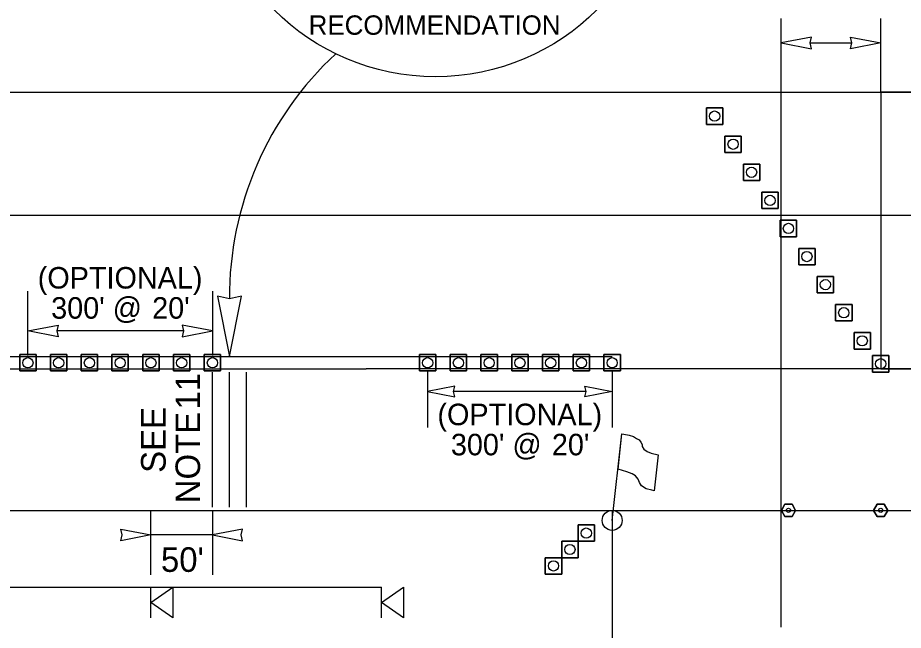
# Model space of a CAD drawing. Extents: x 99998.9 to 100095.7, y 99995 to 100010.7.
# Drawn here: x 100042.344 to 100045.223, y 100005.742 to 100007.734 of the extents above; entities that cross this region are included whole.
import ezdxf

# ---------------------------------------------------------------- set-up
doc = ezdxf.new("R2010")
doc.units = 0
for name, color, linetype in [('RD_ED_ShoulderPavedEdge', 7, 'Continuous'), ('RD_MK_LineDblYellowCenter', 7, 'Continuous'), ('RD_MK_LineEdgeWhite', 7, 'Continuous'), ('RD_MK_LineNoPass', 7, 'Continuous'), ('RD_MK_LineSkipCenter', 7, 'Continuous'), ('TR_WZ_FlaggingStation', 7, 'Continuous'), ('TR_WZ_PortableSignMountBlk-Org', 7, 'Continuous'), ('TR_WZ_TrafficCone', 7, 'Continuous'), ('TR_WZ_TubularMarker', 7, 'Continuous'), ('TR_WZ_WorkZoneDetails', 7, 'Continuous'), ('TR_WZ_WorkZoneTextCurrent', 7, 'Continuous')]:
    doc.layers.add(name, color=color, linetype=linetype)

msp = doc.modelspace()

# ---------------------------------------------------------------- linework, layer by layer
at = {"layer": 'RD_ED_ShoulderPavedEdge'}
msp.add_line((100040.1076, 100007.4923), (100055.6424, 100007.4923), dxfattribs=at)
at = {"layer": 'RD_MK_LineDblYellowCenter'}
for p, q in [((100040.1282, 100006.6323), (100043.4767, 100006.6323)), ((100040.0869, 100006.5923), (100043.4767, 100006.5923))]:
    msp.add_line(p, q, dxfattribs=at)
at = {"layer": 'RD_MK_LineEdgeWhite'}
for p, q in [((100040.1076, 100007.0923), (100055.6424, 100007.0923)), ((100040.1076, 100006.1323), (100055.6424, 100006.1323))]:
    msp.add_line(p, q, dxfattribs=at)
at = {"layer": 'RD_MK_LineNoPass'}
msp.add_line((100043.4767, 100006.6323), (100044.2767, 100006.6323), dxfattribs=at)
at = {"layer": 'RD_MK_LineSkipCenter'}
msp.add_lwpolyline([(100051.15, 100006.5923), (100043.4767, 100006.5923)], dxfattribs=at)
at = {"layer": 'TR_WZ_FlaggingStation'}
for p, q in [((100044.2767, 100006.0998), (100044.3087, 100006.3808)), ((100044.2957, 100006.2667), (100044.3087, 100006.3811)), ((100044.4267, 100006.3133), (100044.4134, 100006.1961)), ((100044.2957, 100006.2667), (100044.2957, 100006.2667))]:
    msp.add_line(p, q, dxfattribs=at)
for points in [[(100044.3087, 100006.3811), (100044.3145, 100006.3798), (100044.3323, 100006.3764), (100044.3461, 100006.3722), (100044.3558, 100006.3661), (100044.3643, 100006.3614), (100044.37, 100006.3546), (100044.3743, 100006.3467), (100044.3748, 100006.3405), (100044.3802, 100006.3313), (100044.391, 100006.3239), (100044.4034, 100006.3187), (100044.4267, 100006.3133)], [(100044.4134, 100006.1961), (100044.4052, 100006.1975), (100044.3876, 100006.2021), (100044.3719, 100006.2126), (100044.3654, 100006.2232), (100044.3615, 100006.2335), (100044.3524, 100006.2444), (100044.3414, 100006.2506), (100044.3241, 100006.2577), (100044.2957, 100006.2667)]]:
    msp.add_lwpolyline(points, dxfattribs=at)
msp.add_circle((100044.2767, 100006.0998), 0.0325, dxfattribs=at)
at = {"layer": 'TR_WZ_PortableSignMountBlk-Org'}
for p, q in [((100042.7767, 100005.7824), (100042.7767, 100005.8824)), ((100043.5267, 100005.7824), (100043.5267, 100005.8824))]:
    msp.add_line(p, q, dxfattribs=at)
for points in [[(100042.7767, 100005.8323), (100042.8485, 100005.8824), (100042.8485, 100005.7824)], [(100043.5267, 100005.8323), (100043.5985, 100005.8824), (100043.5985, 100005.7824)]]:
    msp.add_lwpolyline(points, close=True, dxfattribs=at)
at = {"layer": 'TR_WZ_TrafficCone'}
for points in [[(100044.6367, 100007.4411), (100044.5834, 100007.4411), (100044.5834, 100007.3877), (100044.6367, 100007.3877), (100044.6367, 100007.4411)], [(100044.6367, 100007.3877), (100044.5834, 100007.3877), (100044.5834, 100007.4411), (100044.6367, 100007.4411), (100044.6367, 100007.3877)], [(100044.6967, 100007.3497), (100044.6434, 100007.3497), (100044.6434, 100007.2964), (100044.6967, 100007.2964), (100044.6967, 100007.3497)], [(100044.6967, 100007.2964), (100044.6434, 100007.2964), (100044.6434, 100007.3497), (100044.6967, 100007.3497), (100044.6967, 100007.2964)], [(100044.7567, 100007.2584), (100044.7034, 100007.2584), (100044.7034, 100007.2051), (100044.7567, 100007.2051), (100044.7567, 100007.2584)], [(100044.7567, 100007.2051), (100044.7034, 100007.2051), (100044.7034, 100007.2584), (100044.7567, 100007.2584), (100044.7567, 100007.2051)], [(100044.8167, 100007.1671), (100044.7634, 100007.1671), (100044.7634, 100007.1137), (100044.8167, 100007.1137), (100044.8167, 100007.1671)], [(100044.8167, 100007.1137), (100044.7634, 100007.1137), (100044.7634, 100007.1671), (100044.8167, 100007.1671), (100044.8167, 100007.1137)], [(100044.8234, 100007.0757), (100044.8767, 100007.0757), (100044.8767, 100007.0224), (100044.8234, 100007.0224), (100044.8234, 100007.0757)], [(100044.8234, 100007.0224), (100044.8767, 100007.0224), (100044.8767, 100007.0757), (100044.8234, 100007.0757), (100044.8234, 100007.0224)], [(100044.8834, 100006.9844), (100044.9367, 100006.9844), (100044.9367, 100006.9311), (100044.8834, 100006.9311), (100044.8834, 100006.9844)], [(100044.8834, 100006.9311), (100044.9367, 100006.9311), (100044.9367, 100006.9844), (100044.8834, 100006.9844), (100044.8834, 100006.9311)], [(100044.9434, 100006.8931), (100044.9967, 100006.8931), (100044.9967, 100006.8397), (100044.9434, 100006.8397), (100044.9434, 100006.8931)], [(100044.9434, 100006.8397), (100044.9967, 100006.8397), (100044.9967, 100006.8931), (100044.9434, 100006.8931), (100044.9434, 100006.8397)], [(100045.0034, 100006.8017), (100045.0567, 100006.8017), (100045.0567, 100006.7484), (100045.0034, 100006.7484), (100045.0034, 100006.8017)], [(100045.0034, 100006.7484), (100045.0567, 100006.7484), (100045.0567, 100006.8017), (100045.0034, 100006.8017), (100045.0034, 100006.7484)], [(100045.0634, 100006.7104), (100045.1167, 100006.7104), (100045.1167, 100006.6571), (100045.0634, 100006.6571), (100045.0634, 100006.7104)], [(100045.0634, 100006.6571), (100045.1167, 100006.6571), (100045.1167, 100006.7104), (100045.0634, 100006.7104), (100045.0634, 100006.6571)], [(100042.4033, 100006.639), (100042.35, 100006.639), (100042.35, 100006.5857), (100042.4033, 100006.5857), (100042.4033, 100006.639)], [(100042.4033, 100006.5857), (100042.35, 100006.5857), (100042.35, 100006.639), (100042.4033, 100006.639), (100042.4033, 100006.5857)], [(100042.5033, 100006.639), (100042.45, 100006.639), (100042.45, 100006.5857), (100042.5033, 100006.5857), (100042.5033, 100006.639)], [(100042.5033, 100006.5857), (100042.45, 100006.5857), (100042.45, 100006.639), (100042.5033, 100006.639), (100042.5033, 100006.5857)], [(100042.6033, 100006.639), (100042.55, 100006.639), (100042.55, 100006.5857), (100042.6033, 100006.5857), (100042.6033, 100006.639)], [(100042.6033, 100006.5857), (100042.55, 100006.5857), (100042.55, 100006.639), (100042.6033, 100006.639), (100042.6033, 100006.5857)], [(100042.7033, 100006.639), (100042.65, 100006.639), (100042.65, 100006.5857), (100042.7033, 100006.5857), (100042.7033, 100006.639)], [(100042.7033, 100006.5857), (100042.65, 100006.5857), (100042.65, 100006.639), (100042.7033, 100006.639), (100042.7033, 100006.5857)], [(100042.8033, 100006.639), (100042.75, 100006.639), (100042.75, 100006.5857), (100042.8033, 100006.5857), (100042.8033, 100006.639)], [(100042.8033, 100006.5857), (100042.75, 100006.5857), (100042.75, 100006.639), (100042.8033, 100006.639), (100042.8033, 100006.5857)], [(100042.9033, 100006.639), (100042.85, 100006.639), (100042.85, 100006.5857), (100042.9033, 100006.5857), (100042.9033, 100006.639)], [(100042.9033, 100006.5857), (100042.85, 100006.5857), (100042.85, 100006.639), (100042.9033, 100006.639), (100042.9033, 100006.5857)], [(100043.0033, 100006.639), (100042.95, 100006.639), (100042.95, 100006.5857), (100043.0033, 100006.5857), (100043.0033, 100006.639)], [(100043.0033, 100006.5857), (100042.95, 100006.5857), (100042.95, 100006.639), (100043.0033, 100006.639), (100043.0033, 100006.5857)], [(100043.7033, 100006.639), (100043.65, 100006.639), (100043.65, 100006.5857), (100043.7033, 100006.5857), (100043.7033, 100006.639)], [(100043.7033, 100006.5857), (100043.65, 100006.5857), (100043.65, 100006.639), (100043.7033, 100006.639), (100043.7033, 100006.5857)], [(100043.8033, 100006.639), (100043.75, 100006.639), (100043.75, 100006.5857), (100043.8033, 100006.5857), (100043.8033, 100006.639)], [(100043.8033, 100006.5857), (100043.75, 100006.5857), (100043.75, 100006.639), (100043.8033, 100006.639), (100043.8033, 100006.5857)], [(100043.9033, 100006.639), (100043.85, 100006.639), (100043.85, 100006.5857), (100043.9033, 100006.5857), (100043.9033, 100006.639)], [(100043.9033, 100006.5857), (100043.85, 100006.5857), (100043.85, 100006.639), (100043.9033, 100006.639), (100043.9033, 100006.5857)], [(100044.0033, 100006.639), (100043.95, 100006.639), (100043.95, 100006.5857), (100044.0033, 100006.5857), (100044.0033, 100006.639)], [(100044.0033, 100006.5857), (100043.95, 100006.5857), (100043.95, 100006.639), (100044.0033, 100006.639), (100044.0033, 100006.5857)], [(100044.1033, 100006.639), (100044.05, 100006.639), (100044.05, 100006.5857), (100044.1033, 100006.5857), (100044.1033, 100006.639)], [(100044.1033, 100006.5857), (100044.05, 100006.5857), (100044.05, 100006.639), (100044.1033, 100006.639), (100044.1033, 100006.5857)], [(100044.2033, 100006.639), (100044.15, 100006.639), (100044.15, 100006.5857), (100044.2033, 100006.5857), (100044.2033, 100006.639)], [(100044.2033, 100006.5857), (100044.15, 100006.5857), (100044.15, 100006.639), (100044.2033, 100006.639), (100044.2033, 100006.5857)], [(100044.3033, 100006.639), (100044.25, 100006.639), (100044.25, 100006.5857), (100044.3033, 100006.5857), (100044.3033, 100006.639)], [(100044.3033, 100006.5857), (100044.25, 100006.5857), (100044.25, 100006.639), (100044.3033, 100006.639), (100044.3033, 100006.5857)], [(100045.1234, 100006.6357), (100045.1767, 100006.6357), (100045.1767, 100006.5823), (100045.1234, 100006.5823), (100045.1234, 100006.6357)], [(100045.1234, 100006.5823), (100045.1767, 100006.5823), (100045.1767, 100006.6357), (100045.1234, 100006.6357), (100045.1234, 100006.5823)], [(100044.166, 100006.085), (100044.2193, 100006.085), (100044.2193, 100006.0317), (100044.166, 100006.0317), (100044.166, 100006.085)], [(100044.166, 100006.0317), (100044.2193, 100006.0317), (100044.2193, 100006.085), (100044.166, 100006.085), (100044.166, 100006.0317)], [(100044.1127, 100006.0317), (100044.166, 100006.0317), (100044.166, 100005.9783), (100044.1127, 100005.9783), (100044.1127, 100006.0317)], [(100044.1127, 100005.9783), (100044.166, 100005.9783), (100044.166, 100006.0317), (100044.1127, 100006.0317), (100044.1127, 100005.9783)], [(100044.0593, 100005.9783), (100044.1127, 100005.9783), (100044.1127, 100005.925), (100044.0593, 100005.925), (100044.0593, 100005.9783)], [(100044.0593, 100005.925), (100044.1127, 100005.925), (100044.1127, 100005.9783), (100044.0593, 100005.9783), (100044.0593, 100005.925)]]:
    msp.add_lwpolyline(points, dxfattribs=at)
for centre in [(100044.61, 100007.4144), (100044.67, 100007.3231), (100044.73, 100007.2317), (100044.79, 100007.1404), (100044.85, 100007.0491), (100044.91, 100006.9577), (100044.97, 100006.8664), (100045.03, 100006.7751), (100045.09, 100006.6837), (100042.3767, 100006.6123), (100042.4767, 100006.6123), (100042.5767, 100006.6123), (100042.6767, 100006.6123), (100042.7767, 100006.6123), (100042.8767, 100006.6123), (100042.9767, 100006.6123), (100043.6767, 100006.6123), (100043.7767, 100006.6123), (100043.8767, 100006.6123), (100043.9767, 100006.6123), (100044.0767, 100006.6123), (100044.1767, 100006.6123), (100044.2767, 100006.6123), (100045.15, 100006.609), (100044.1927, 100006.0583), (100044.1393, 100006.005), (100044.086, 100005.9517)]:
    msp.add_circle(centre, 0.0167, dxfattribs=at)
at = {"layer": 'TR_WZ_TubularMarker'}
for points in [[(100044.8269, 100006.1323), (100044.8385, 100006.1523), (100044.8616, 100006.1523), (100044.8731, 100006.1323), (100044.8616, 100006.1123), (100044.8385, 100006.1123)], [(100045.1269, 100006.1323), (100045.1385, 100006.1523), (100045.1616, 100006.1523), (100045.1731, 100006.1323), (100045.1616, 100006.1123), (100045.1385, 100006.1123)]]:
    msp.add_lwpolyline(points, close=True, dxfattribs=at)
for points in [[(100044.8385, 100006.1123), (100044.8616, 100006.1123), (100044.8731, 100006.1323), (100044.8616, 100006.1523), (100044.8385, 100006.1523), (100044.8269, 100006.1323), (100044.8385, 100006.1123)], [(100045.1385, 100006.1123), (100045.1616, 100006.1123), (100045.1731, 100006.1323), (100045.1616, 100006.1523), (100045.1385, 100006.1523), (100045.1269, 100006.1323), (100045.1385, 100006.1123)]]:
    msp.add_lwpolyline(points, dxfattribs=at)
for centre in [(100044.85, 100006.1323), (100045.15, 100006.1323)]:
    msp.add_circle(centre, 0.00667, dxfattribs=at)
at = {"layer": 'TR_WZ_WorkZoneDetails'}
for p, q in [((100044.8267, 100005.7523), (100044.8267, 100007.7323)), ((100045.15, 100007.4923), (100045.15, 100007.7323)), ((100044.9204, 100007.6523), (100045.0563, 100007.6523)), ((100042.3767, 100006.6357), (100042.3767, 100006.8457)), ((100042.9767, 100006.8457), (100042.9767, 100006.6357)), ((100042.8829, 100006.7157), (100042.4704, 100006.7157)), ((100043.6767, 100006.5857), (100043.6767, 100006.4023)), ((100044.2767, 100006.5857), (100044.2767, 100006.4023)), ((100042.9767, 100006.1423), (100042.9767, 100006.5823)), ((100043.0323, 100006.1423), (100043.0323, 100006.5823)), ((100043.0872, 100006.1423), (100043.0872, 100006.5823)), ((100044.1923, 100006.5193), (100043.761, 100006.5193)), ((100042.7767, 100005.9223), (100042.7767, 100006.1323)), ((100042.9767, 100006.1323), (100042.9767, 100005.9223)), ((100044.2767, 100006.1323), (100044.2767, 100005.4923)), ((100042.9767, 100006.0523), (100042.7767, 100006.0523)), ((100040.5267, 100005.8824), (100043.5267, 100005.8824))]:
    msp.add_line(p, q, dxfattribs=at)
for points in [[(100044.8267, 100007.6523), (100044.9249, 100007.6331), (100044.9204, 100007.6523), (100044.9249, 100007.6716)], [(100045.15, 100007.6523), (100045.0517, 100007.6331), (100045.0563, 100007.6523), (100045.0517, 100007.6716)], [(100045.15, 100007.4923), (100045.15, 100006.5923), (100049.9338, 100006.5923), (100049.9338, 100007.4923)], [(100043.0323, 100006.6323), (100043.0708, 100006.8289), (100043.0323, 100006.8198), (100042.9937, 100006.8289)], [(100042.3767, 100006.7157), (100042.4749, 100006.7349), (100042.4704, 100006.7157), (100042.4749, 100006.6964)], [(100042.9767, 100006.7157), (100042.8784, 100006.7349), (100042.8829, 100006.7157), (100042.8784, 100006.6964)], [(100043.6767, 100006.5193), (100043.7651, 100006.502), (100043.761, 100006.5193), (100043.7651, 100006.5367)], [(100044.2767, 100006.5193), (100044.1882, 100006.502), (100044.1923, 100006.5193), (100044.1882, 100006.5367)], [(100042.7767, 100006.0523), (100042.6784, 100006.0331), (100042.6829, 100006.0523), (100042.6784, 100006.0716)], [(100042.9767, 100006.0523), (100043.0749, 100006.0331), (100043.0704, 100006.0523), (100043.0749, 100006.0716)]]:
    msp.add_lwpolyline(points, close=True, dxfattribs=at)
msp.add_circle((100043.7022, 100008.2843), 0.742, dxfattribs=at)
msp.add_arc((100044.1081, 100006.8268), 1.0759, 132.7426, 180.3733, dxfattribs=at)

# ---------------------------------------------------------------- texts
msp.add_text('RECOMMENDATION', height=0.063, dxfattribs=at).set_placement((100043.2898, 100007.679))
for s, p in [('11', (100042.9367, 100006.4604)), ('SEE', (100042.8247, 100006.2544)), ('NOTE', (100042.9367, 100006.1555))]:
    msp.add_text(s, height=0.08, rotation=90, dxfattribs=at).set_placement(p)
at = {"layer": 'TR_WZ_WorkZoneTextCurrent'}
for s, height, p in [('(OPTIONAL)', 0.07, (100042.4087, 100006.8537)), ("300' @", 0.07, (100042.4524, 100006.7557)), ("20'", 0.07, (100042.7808, 100006.7557)), ('(OPTIONAL)', 0.07, (100043.7085, 100006.4093)), ("300' @", 0.07, (100043.7523, 100006.3113)), ("20'", 0.07, (100044.0807, 100006.3113)), ("50'", 0.08, (100042.8094, 100005.9323))]:
    msp.add_text(s, height=height, dxfattribs=at).set_placement(p)

doc.saveas('drawing.dxf')
